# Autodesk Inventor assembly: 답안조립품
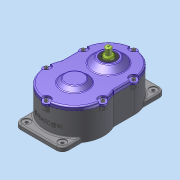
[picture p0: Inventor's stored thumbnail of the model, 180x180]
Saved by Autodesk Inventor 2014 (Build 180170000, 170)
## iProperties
Created: 2025-09
Part Number: 답안조립품
Document SubType Name: Assembly
Designer: dg
Author: dg
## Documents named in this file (19)
- C:\Users\dg\Desktop\750903V1013\답안조립품.iam
- C:\Users\dg\Desktop\750903V1013\본체.ipt
- C:\Users\dg\Desktop\750903V1013\가져온 구성요소\구동 축\구동 축.ipt
- C:\Users\dg\Desktop\750903V1013\가져온 구성요소\슬롯 축\슬롯 축.ipt
- C:\Users\dg\Desktop\750903V1013\가져온 구성요소\평행 키 6x6x14\평행 키 6x6x14.ipt
- C:\Users\dg\Desktop\750903V1013\가져온 구성요소\구동 휠\구동 휠.ipt
- C:\Users\dg\Desktop\750903V1013\가져온 구성요소\깊은 홈 볼 베어링 6904\깊은 홈 볼 베어링 6904.ipt
- C:\Users\dg\Desktop\750903V1013\가져온 구성요소\슬롯\슬롯.ipt
- C:\Users\dg\Desktop\750903V1013\가져온 구성요소\6각 구멍붙이 볼트 M6x12\6각 구멍붙이 볼트 M6x12.ipt
- C:\Users\dg\Desktop\750903V1013\가져온 구성요소\스러스트 볼 베어링 51102\스러스트 볼 베어링 51102.ipt
- C:\Users\dg\Desktop\750903V1013\가져온 구성요소\어댑터\어댑터.ipt
- C:\Users\dg\Desktop\750903V1013\가져온 구성요소\칼라\칼라.ipt
- C:\Users\dg\Desktop\750903V1013\가져온 구성요소\스프링 와셔 M3\스프링 와셔 M3.ipt
- C:\Users\dg\Desktop\750903V1013\가져온 구성요소\육각 너트 M3\육각 너트 M3.ipt
- C:\Users\dg\Desktop\750903V1013\가져온 구성요소\캠 플로워\캠 플로워.ipt
- C:\Users\dg\Desktop\750903V1013\가져온 구성요소\평 와셔 M3\평 와셔 M3.ipt
- C:\Users\dg\Desktop\750903V1013\가져온 구성요소\오일 실 20 35 8\오일 실 20 35 8.ipt
- C:\Users\dg\Desktop\750903V1013\가져온 구성요소\커버\커버.ipt
- C:\Users\dg\Desktop\750903V1013\가져온 구성요소\6각 구멍붙이 볼트 M4x10\6각 구멍붙이 볼트 M4x10.ipt
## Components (9 placed, 4 different names)
1. 구동 축:1
2. 구동 휠:1 — 각도:1
3. 6각 구멍붙이 볼트 M6x12:1
4. 6각 구멍붙이 볼트 M4x10:1
5. 6각 구멍붙이 볼트 M4x10:2
6. 6각 구멍붙이 볼트 M4x10:3
7. 6각 구멍붙이 볼트 M4x10:4
8. 6각 구멍붙이 볼트 M4x10:5
9. 6각 구멍붙이 볼트 M4x10:6
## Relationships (1: Angle 1)
- 각도:1 [Angle]: 구동 휠:1
